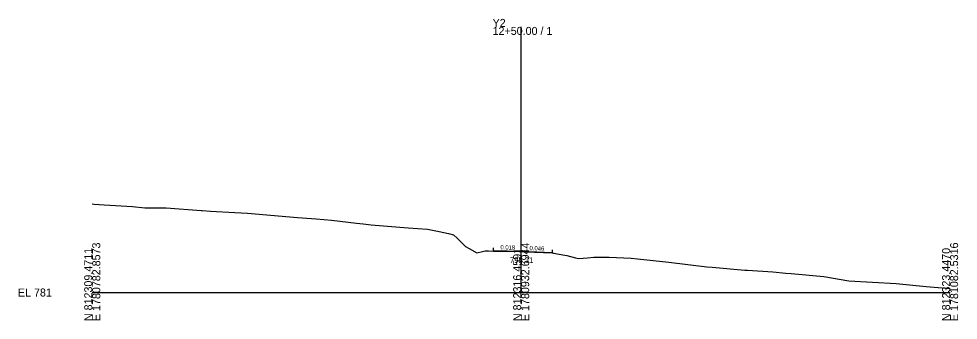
# Model space of a CAD drawing. Extents: x -26 to 303, y -10 to 3096.
# Drawn here: x -25.7 to 302.8, y 2990.3 to 3095.8 of the extents above; entities that cross this region are included whole.
import ezdxf

# ---------------------------------------------------------------- set-up
doc = ezdxf.new("R2010")
doc.units = 0
for name, color, linetype in [('Exist Cross Section Cell', 7, 'Continuous'), ('Exist XS Center Line Elevation Label', 7, 'Continuous'), ('Exist XS Ground Line', 7, 'Continuous'), ('Prop XS Dump Level', 7, 'Continuous'), ('Prop XS EOT Tick Mark', 7, 'Continuous'), ('Prop XS Finish Grade Pavement', 7, 'Continuous'), ('Prop XS SE Text', 7, 'Continuous')]:
    doc.layers.add(name, color=color, linetype=linetype)

msp = doc.modelspace()

# ---------------------------------------------------------------- linework, layer by layer
at = {"layer": 'Exist Cross Section Cell'}
for p, q in [((150, 3000), (150, 3092.92)), ((0, 3000), (150, 3000)), ((150, 3000), (300, 3000))]:
    msp.add_line(p, q, dxfattribs=at)
at = {"layer": 'Exist XS Ground Line'}
for p, q in [((0, 3030.97), (0.69, 3030.91)), ((0.69, 3030.91), (4.15, 3030.68)), ((4.15, 3030.68), (14.13, 3030.04)), ((14.13, 3030.04), (18.36, 3029.65)), ((18.36, 3029.65), (18.93, 3029.65)), ((18.93, 3029.65), (22.63, 3029.65)), ((22.63, 3029.65), (25.81, 3029.6)), ((25.81, 3029.6), (38.09, 3028.66)), ((38.09, 3028.66), (38.4, 3028.64)), ((38.4, 3028.64), (41.32, 3028.5)), ((41.32, 3028.5), (49.91, 3028.05)), ((49.91, 3028.05), (54.27, 3027.71)), ((54.27, 3027.71), (71.79, 3026.28)), ((71.79, 3026.28), (78.25, 3025.8)), ((78.25, 3025.8), (83.64, 3025.33)), ((83.64, 3025.33), (92.38, 3024.29)), ((92.38, 3024.29), (94.71, 3023.97)), ((94.71, 3023.97), (97.56, 3023.69)), ((97.56, 3023.69), (110.49, 3022.64)), ((110.49, 3022.64), (117.27, 3022.19)), ((117.27, 3022.19), (121.29, 3021.31)), ((121.29, 3021.31), (124.61, 3020.61)), ((124.61, 3020.61), (126.35, 3020.21)), ((126.35, 3020.21), (127.6, 3019.03)), ((127.6, 3019.03), (130.54, 3016.12)), ((130.54, 3016.12), (131.83, 3015.45)), ((131.83, 3015.45), (134.49, 3013.88)), ((134.49, 3013.88), (136.49, 3014.35)), ((136.49, 3014.35), (137.36, 3014.55)), ((137.36, 3014.55), (138.55, 3014.53)), ((138.55, 3014.53), (140.32, 3014.49)), ((140.32, 3014.49), (149.26, 3014.32)), ((149.26, 3014.32), (150, 3014.31)), ((150, 3014.31), (150.38, 3014.31)), ((150.38, 3014.31), (151.54, 3014.26)), ((151.54, 3014.26), (161, 3013.83)), ((161, 3013.83), (162.55, 3013.49)), ((162.55, 3013.49), (165.94, 3012.9)), ((165.94, 3012.9), (168.99, 3012.19)), ((168.99, 3012.19), (170.2, 3011.85)), ((170.2, 3011.85), (173.19, 3012.1)), ((173.19, 3012.1), (175.4, 3012.31)), ((175.4, 3012.31), (176.43, 3012.34)), ((176.43, 3012.34), (178.34, 3012.33)), ((178.34, 3012.33), (180.81, 3012.33)), ((180.81, 3012.33), (188.43, 3011.98)), ((188.43, 3011.98), (190.65, 3011.77)), ((190.65, 3011.77), (201.62, 3010.59)), ((201.62, 3010.59), (214.95, 3008.98)), ((214.95, 3008.98), (216.83, 3008.82)), ((216.83, 3008.82), (228.16, 3007.86)), ((228.16, 3007.86), (229.16, 3007.78)), ((229.16, 3007.78), (237.96, 3007.18)), ((237.96, 3007.18), (242.5, 3006.78)), ((242.5, 3006.78), (244.4, 3006.61)), ((244.4, 3006.61), (255.79, 3005.61)), ((255.79, 3005.61), (264.62, 3004.08)), ((264.62, 3004.08), (281.14, 3003.2)), ((281.14, 3003.2), (291.66, 3002.16)), ((291.66, 3002.16), (300, 3001.46))]:
    msp.add_line(p, q, dxfattribs=at)
at = {"layer": 'Prop XS Dump Level'}
for p, q in [((140.32, 3014.64), (150, 3014.46)), ((150, 3014.46), (161, 3013.96))]:
    msp.add_line(p, q, dxfattribs=at)
at = {"layer": 'Prop XS EOT Tick Mark'}
for p, q in [((140.32, 3014.64), (140.32, 3015.64)), ((161, 3013.96), (161, 3014.96))]:
    msp.add_line(p, q, dxfattribs=at)
at = {"layer": 'Prop XS Finish Grade Pavement'}
for p, q in [((140.32, 3014.64), (150, 3014.46)), ((150, 3014.46), (161, 3013.96))]:
    msp.add_line(p, q, dxfattribs=at)

# ---------------------------------------------------------------- texts
at = {"layer": 'Exist Cross Section Cell'}
for s, p in [('Y2', (140, 3092.92)), ('12+50.00 / 1', (140, 3090.12)), ('EL 781', (-26, 2998.6))]:
    msp.add_text(s, height=2.8, dxfattribs=at).set_placement(p)
for s, p in [('E 1780782.8573', (2.8, 2990)), ('E 1780932.6944', (152.8, 2990)), ('E 1781082.5316', (302.8, 2990)), ('N 812309.4711', (0, 2990)), ('N 812316.4591', (150, 2990)), ('N 812323.4470', (300, 2990))]:
    msp.add_text(s, height=2.8, rotation=90, dxfattribs=at).set_placement(p)
at = {"layer": 'Exist XS Center Line Elevation Label'}
msp.add_text('795.31', height=2, dxfattribs=at).set_placement((146.08, 3010.31))
at = {"layer": 'Prop XS Dump Level'}
for p in [(140.32, 3014.19), (161, 3013.53)]:
    msp.add_text('Eop', height=0.3, dxfattribs=at).set_placement(p)
at = {"layer": 'Prop XS SE Text'}
for s, rotation, p in [('0.018', 358.9573, (142.73, 3015.09)), ('0.046', 357.3891, (152.89, 3014.83))]:
    msp.add_text(s, height=1.5, rotation=rotation, dxfattribs=at).set_placement(p)

doc.saveas('drawing.dxf')
